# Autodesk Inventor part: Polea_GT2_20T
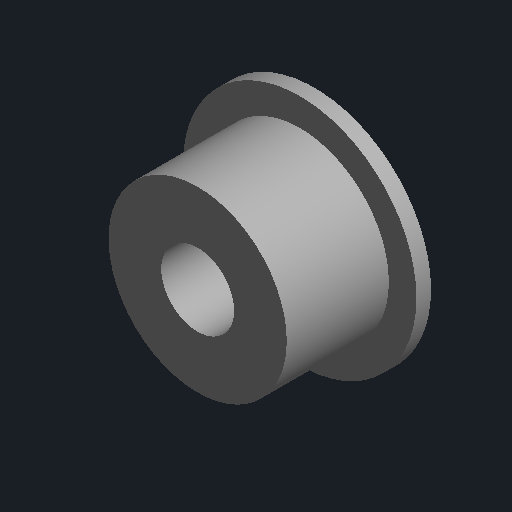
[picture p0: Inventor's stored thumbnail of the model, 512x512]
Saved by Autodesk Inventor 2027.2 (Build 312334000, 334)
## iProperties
Part Number: Polea_GT2_20T
Material: Genérico
Document SubType Name: Modelado
Designer: Usuario
Appearance: Por defecto
Author: Usuario
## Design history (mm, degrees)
sketch "Boceto1"
  geometry: C1 r 6.11 at (0, 0); C2 r 2.5 at (0, 0)
  constraints: 2 centre point
extrude "Extrusión1" new body sketch "Boceto1" distance "d0" = 7; taper "d1" = 0 deg
sketch "Boceto2"
  geometry: C1 r 8 at (0, 0); C2 r 2.5 at (0, 0)
  constraints: 2 centre point
extrude "Extrusión2" join sketch "Boceto2" distance "d2" = 1; taper "d3" = 0 deg
node "Sólido1"
node "Cuerpos sólidos"
node "Cuerpos de superficie"
